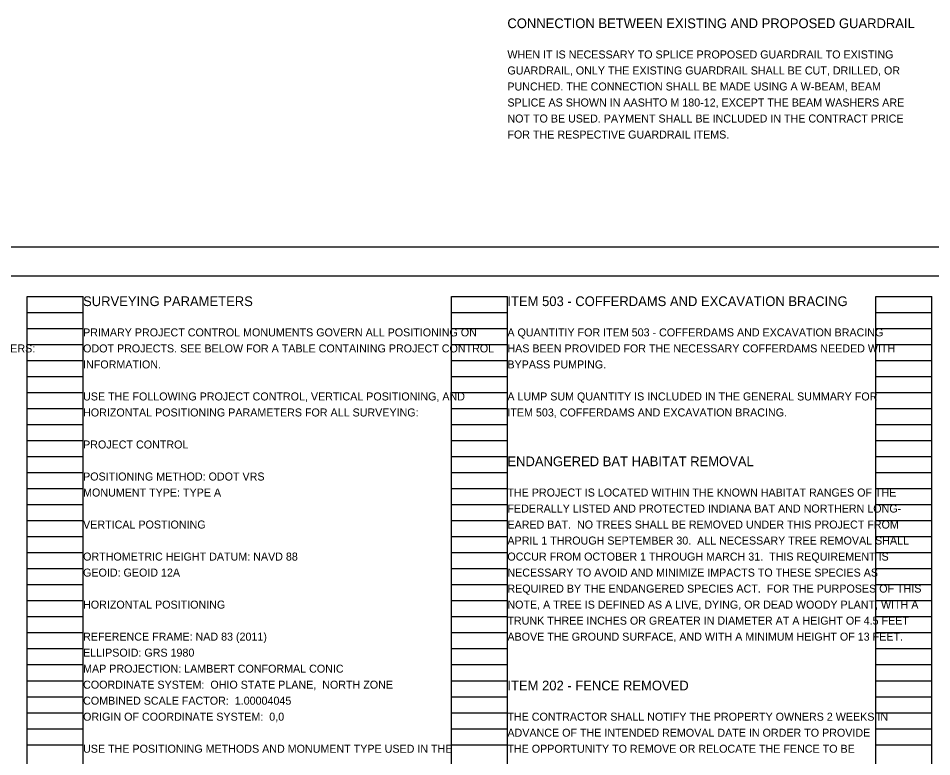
# Model space of a CAD drawing. Extents: x -3.4 to 43.7, y 0 to 26.
# Drawn here: x 8.69 to 24.66, y 13.09 to 26 of the extents above; entities that cross this region are included whole.
import ezdxf

# ---------------------------------------------------------------- set-up
doc = ezdxf.new("R2010")
doc.units = 0
for name, color, linetype in [('SH_Border', 7, 'Continuous'), ('SH_Cut_Line', 7, 'Continuous'), ('SH_Data', 7, 'Continuous'), ('SH_Text', 7, 'Continuous')]:
    doc.layers.add(name, color=color, linetype=linetype)

msp = doc.modelspace()

# ---------------------------------------------------------------- linework, layer by layer
at = {"layer": 'SH_Border'}
msp.add_lwpolyline([(1.5, 21.5), (33.5, 21.5), (33.5, 0.5), (1.5, 0.5)], close=True, dxfattribs=at)
at = {"layer": 'SH_Cut_Line'}
msp.add_lwpolyline([(0, 0), (34, 0), (34, 22), (0, 22)], close=True, dxfattribs=at)
at = {"layer": 'SH_Data'}
for p, q in [((8.84, 0.98), (8.84, 21.14)), ((8.84, 21.14), (9.82, 21.14)), ((9.82, 0.98), (9.82, 21.14)), ((16.26, 0.98), (16.26, 21.14)), ((16.26, 21.14), (17.24, 21.14)), ((17.24, 0.98), (17.24, 21.14)), ((23.68, 0.98), (23.68, 21.14)), ((23.68, 21.14), (24.66, 21.14)), ((24.66, 0.98), (24.66, 21.14)), ((8.84, 20.86), (9.82, 20.86)), ((16.26, 20.86), (17.24, 20.86)), ((23.68, 20.86), (24.66, 20.86)), ((8.84, 20.58), (9.82, 20.58)), ((16.26, 20.58), (17.24, 20.58)), ((23.68, 20.58), (24.66, 20.58)), ((8.84, 20.3), (9.82, 20.3)), ((16.26, 20.3), (17.24, 20.3)), ((23.68, 20.3), (24.66, 20.3)), ((8.84, 20.02), (9.82, 20.02)), ((16.26, 20.02), (17.24, 20.02)), ((23.68, 20.02), (24.66, 20.02)), ((8.84, 19.74), (9.82, 19.74)), ((16.26, 19.74), (17.24, 19.74)), ((23.68, 19.74), (24.66, 19.74)), ((8.84, 19.46), (9.82, 19.46)), ((16.26, 19.46), (17.24, 19.46)), ((23.68, 19.46), (24.66, 19.46)), ((8.84, 19.18), (9.82, 19.18)), ((16.26, 19.18), (17.24, 19.18)), ((23.68, 19.18), (24.66, 19.18)), ((8.84, 18.9), (9.82, 18.9)), ((16.26, 18.9), (17.24, 18.9)), ((23.68, 18.9), (24.66, 18.9)), ((8.84, 18.62), (9.82, 18.62)), ((16.26, 18.62), (17.24, 18.62)), ((23.68, 18.62), (24.66, 18.62)), ((8.84, 18.34), (9.82, 18.34)), ((16.26, 18.34), (17.24, 18.34)), ((23.68, 18.34), (24.66, 18.34)), ((8.84, 18.06), (9.82, 18.06)), ((16.26, 18.06), (17.24, 18.06)), ((23.68, 18.06), (24.66, 18.06)), ((8.84, 17.78), (9.82, 17.78)), ((16.26, 17.78), (17.24, 17.78)), ((23.68, 17.78), (24.66, 17.78)), ((8.84, 17.5), (9.82, 17.5)), ((16.26, 17.5), (17.24, 17.5)), ((23.68, 17.5), (24.66, 17.5)), ((8.84, 17.22), (9.82, 17.22)), ((16.26, 17.22), (17.24, 17.22)), ((23.68, 17.22), (24.66, 17.22)), ((8.84, 16.94), (9.82, 16.94)), ((16.26, 16.94), (17.24, 16.94)), ((23.68, 16.94), (24.66, 16.94)), ((8.84, 16.66), (9.82, 16.66)), ((16.26, 16.66), (17.24, 16.66)), ((23.68, 16.66), (24.66, 16.66)), ((8.84, 16.38), (9.82, 16.38)), ((16.26, 16.38), (17.24, 16.38)), ((23.68, 16.38), (24.66, 16.38)), ((8.84, 16.1), (9.82, 16.1)), ((16.26, 16.1), (17.24, 16.1)), ((23.68, 16.1), (24.66, 16.1)), ((8.84, 15.82), (9.82, 15.82)), ((16.26, 15.82), (17.24, 15.82)), ((23.68, 15.82), (24.66, 15.82)), ((8.84, 15.54), (9.82, 15.54)), ((16.26, 15.54), (17.24, 15.54)), ((23.68, 15.54), (24.66, 15.54)), ((8.84, 15.26), (9.82, 15.26)), ((16.26, 15.26), (17.24, 15.26)), ((23.68, 15.26), (24.66, 15.26)), ((8.84, 14.98), (9.82, 14.98)), ((16.26, 14.98), (17.24, 14.98)), ((23.68, 14.98), (24.66, 14.98)), ((8.84, 14.7), (9.82, 14.7)), ((16.26, 14.7), (17.24, 14.7)), ((23.68, 14.7), (24.66, 14.7)), ((8.84, 14.42), (9.82, 14.42)), ((16.26, 14.42), (17.24, 14.42)), ((23.68, 14.42), (24.66, 14.42)), ((8.84, 14.14), (9.82, 14.14)), ((16.26, 14.14), (17.24, 14.14)), ((23.68, 14.14), (24.66, 14.14)), ((8.84, 13.86), (9.82, 13.86)), ((16.26, 13.86), (17.24, 13.86)), ((23.68, 13.86), (24.66, 13.86)), ((8.84, 13.58), (9.82, 13.58)), ((16.26, 13.58), (17.24, 13.58)), ((23.68, 13.58), (24.66, 13.58)), ((8.84, 13.3), (9.82, 13.3)), ((16.26, 13.3), (17.24, 13.3)), ((23.68, 13.3), (24.66, 13.3))]:
    msp.add_line(p, q, dxfattribs=at)

# ---------------------------------------------------------------- texts
at = {"layer": 'SH_Text'}
for s, height, p in [('CONNECTION BETWEEN EXISTING AND PROPOSED GUARDRAIL', 0.17, (17.24, 25.83)), ('WHEN IT IS NECESSARY TO SPLICE PROPOSED GUARDRAIL TO EXISTING ', 0.14, (17.24, 25.3)), ('GUARDRAIL, ONLY THE EXISTING GUARDRAIL SHALL BE CUT, DRILLED, OR ', 0.14, (17.24, 25.02)), ('PUNCHED. THE CONNECTION SHALL BE MADE USING A W-BEAM, BEAM ', 0.14, (17.24, 24.74)), ('SPLICE AS SHOWN IN AASHTO M 180-12, EXCEPT THE BEAM WASHERS ARE ', 0.14, (17.24, 24.46)), ('NOT TO BE USED. PAYMENT SHALL BE INCLUDED IN THE CONTRACT PRICE ', 0.14, (17.24, 24.18)), ('FOR THE RESPECTIVE GUARDRAIL ITEMS.', 0.14, (17.24, 23.9)), ('SURVEYING PARAMETERS', 0.17, (9.82, 20.97)), ('ITEM 503 - COFFERDAMS AND EXCAVATION BRACING', 0.17, (17.24, 20.97)), ('PRIMARY PROJECT CONTROL MONUMENTS GOVERN ALL POSITIONING ON ', 0.14, (9.82, 20.44)), ('A QUANTITIY FOR ITEM 503 - COFFERDAMS AND EXCAVATION BRACING ', 0.14, (17.24, 20.44)), ('CONSTRUCTION LIMITS TOGETHER WITH THEIR RESPECTIVE OWNERS:', 0.14, (2.4, 20.16)), ('ODOT PROJECTS. SEE BELOW FOR A TABLE CONTAINING PROJECT CONTROL ', 0.14, (9.82, 20.16)), ('HAS BEEN PROVIDED FOR THE NECESSARY COFFERDAMS NEEDED WITH ', 0.14, (17.24, 20.16)), ('INFORMATION.', 0.14, (9.82, 19.88)), ('BYPASS PUMPING.', 0.14, (17.24, 19.88)), ('USE THE FOLLOWING PROJECT CONTROL, VERTICAL POSITIONING, AND ', 0.14, (9.82, 19.32)), ('A LUMP SUM QUANTITY IS INCLUDED IN THE GENERAL SUMMARY FOR ', 0.14, (17.24, 19.32)), ('HORIZONTAL POSITIONING PARAMETERS FOR ALL SURVEYING:', 0.14, (9.82, 19.04)), ('ITEM 503, COFFERDAMS AND EXCAVATION BRACING.', 0.14, (17.24, 19.04)), ('PROJECT CONTROL', 0.14, (9.82, 18.48)), ('ENDANGERED BAT HABITAT REMOVAL', 0.17, (17.24, 18.17)), ('POSITIONING METHOD: ODOT VRS', 0.14, (9.82, 17.92)), ('MONUMENT TYPE: TYPE A', 0.14, (9.82, 17.64)), ('THE PROJECT IS LOCATED WITHIN THE KNOWN HABITAT RANGES OF THE ', 0.14, (17.24, 17.64)), ('FEDERALLY LISTED AND PROTECTED INDIANA BAT AND NORTHERN LONG-', 0.14, (17.24, 17.36)), ('VERTICAL POSTIONING', 0.14, (9.82, 17.08)), ('EARED BAT.  NO TREES SHALL BE REMOVED UNDER THIS PROJECT FROM ', 0.14, (17.24, 17.08)), ('APRIL 1 THROUGH SEPTEMBER 30.  ALL NECESSARY TREE REMOVAL SHALL ', 0.14, (17.24, 16.8)), ('ORTHOMETRIC HEIGHT DATUM: NAVD 88', 0.14, (9.82, 16.52)), ('OCCUR FROM OCTOBER 1 THROUGH MARCH 31.  THIS REQUIREMENT IS ', 0.14, (17.24, 16.52)), ('GEOID: GEOID 12A', 0.14, (9.82, 16.24)), ('NECESSARY TO AVOID AND MINIMIZE IMPACTS TO THESE SPECIES AS ', 0.14, (17.24, 16.24)), ('REQUIRED BY THE ENDANGERED SPECIES ACT.  FOR THE PURPOSES OF THIS ', 0.14, (17.24, 15.96)), ('HORIZONTAL POSITIONING', 0.14, (9.82, 15.68)), ('NOTE, A TREE IS DEFINED AS A LIVE, DYING, OR DEAD WOODY PLANT, WITH A ', 0.14, (17.24, 15.68)), ('TRUNK THREE INCHES OR GREATER IN DIAMETER AT A HEIGHT OF 4.5 FEET ', 0.14, (17.24, 15.4)), ('REFERENCE FRAME: NAD 83 (2011)', 0.14, (9.82, 15.12)), ('ABOVE THE GROUND SURFACE, AND WITH A MINIMUM HEIGHT OF 13 FEET. ', 0.14, (17.24, 15.12)), ('ELLIPSOID: GRS 1980', 0.14, (9.82, 14.84)), ('MAP PROJECTION: LAMBERT CONFORMAL CONIC', 0.14, (9.82, 14.56)), ('COORDINATE SYSTEM:  OHIO STATE PLANE,  NORTH ZONE', 0.14, (9.82, 14.28)), ('ITEM 202 - FENCE REMOVED', 0.17, (17.24, 14.25)), ('COMBINED SCALE FACTOR:  1.00004045', 0.14, (9.82, 14)), ('ORIGIN OF COORDINATE SYSTEM:  0,0', 0.14, (9.82, 13.72)), ('THE CONTRACTOR SHALL NOTIFY THE PROPERTY OWNERS 2 WEEKS IN ', 0.14, (17.24, 13.72)), ('ADVANCE OF THE INTENDED REMOVAL DATE IN ORDER TO PROVIDE ', 0.14, (17.24, 13.44)), ('USE THE POSITIONING METHODS AND MONUMENT TYPE USED IN THE ', 0.14, (9.82, 13.16)), ('THE OPPORTUNITY TO REMOVE OR RELOCATE THE FENCE TO BE ', 0.14, (17.24, 13.16))]:
    msp.add_text(s, height=height, dxfattribs=at).set_placement(p)

doc.saveas('drawing.dxf')
